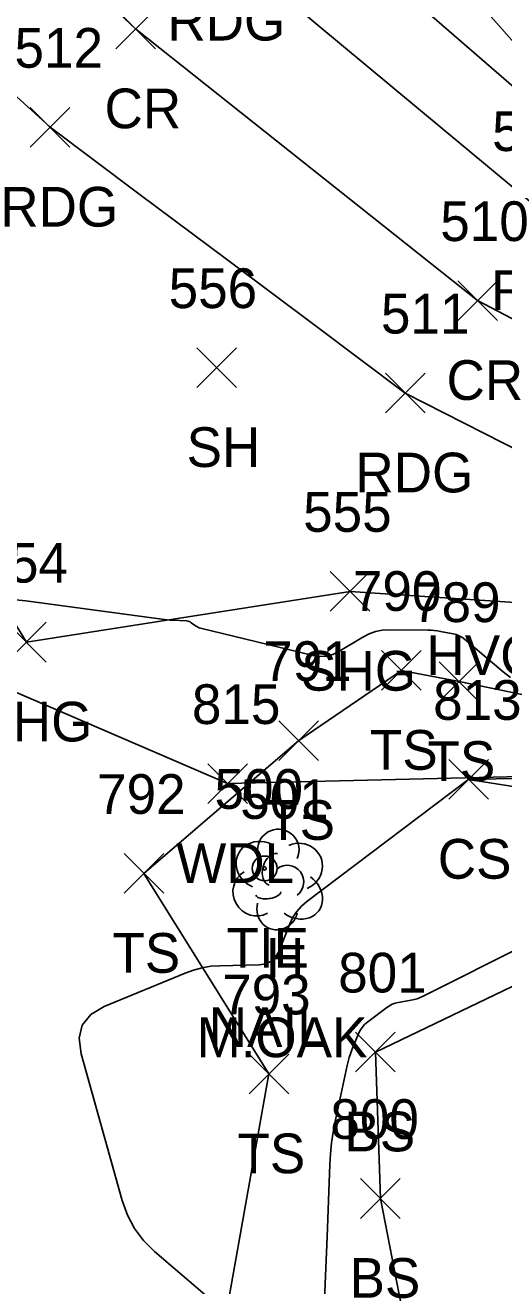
# Model space of a CAD drawing. Extents: x 1592612 to 1596497, y 111838 to 113741.
# Drawn here: x 1592810.3 to 1592834.4, y 113419.9 to 113483.4 of the extents above; entities that cross this region are included whole.
import ezdxf

# ---------------------------------------------------------------- set-up
doc = ezdxf.new("R2010")
doc.units = 0
for name, color, linetype in [('C_A', 7, 'Continuous'), ('C_C', 7, 'Continuous'), ('C_I', 7, 'Continuous'), ('CBP', 7, 'Continuous'), ('L_A', 7, 'Continuous'), ('L_C', 7, 'Continuous'), ('L_I', 7, 'Continuous'), ('L_TIC', 7, 'Continuous'), ('LAWA', 7, 'Continuous'), ('LELB', 7, 'Continuous'), ('LSOGCMI', 7, 'Continuous'), ('LTD', 7, 'Continuous'), ('P_A', 7, 'Continuous'), ('P_I', 7, 'Continuous'), ('P_TIC', 7, 'Continuous'), ('PEU', 7, 'Continuous'), ('PRC', 7, 'Continuous'), ('PSU', 7, 'Continuous'), ('RGR', 7, 'Continuous')]:
    doc.layers.add(name, color=color, linetype=linetype)

msp = doc.modelspace()

# ---------------------------------------------------------------- linework, layer by layer
at = {"layer": 'CBP'}
for radius in [0.625, 0.0833]:
    msp.add_circle((1592822.362, 113440.933), radius, dxfattribs=at)
at = {"layer": 'L_TIC'}
for points in [[(1592818.939, 113465.147), (1592820.939, 113467.147)], [(1592820.939, 113465.147), (1592818.939, 113467.147)], [(1592828.258, 113449.901), (1592830.258, 113451.901)], [(1592830.258, 113449.901), (1592828.258, 113451.901)], [(1592831.164, 113449.338), (1592833.164, 113451.338)], [(1592833.164, 113449.338), (1592831.164, 113451.338)], [(1592823.082, 113446.372), (1592825.082, 113448.372)], [(1592825.082, 113446.372), (1592823.082, 113448.372)], [(1592819.49, 113444.204), (1592821.49, 113446.204)], [(1592821.49, 113444.204), (1592819.49, 113446.204)], [(1592831.649, 113444.415), (1592833.649, 113446.415)], [(1592833.649, 113444.415), (1592831.649, 113446.415)], [(1592815.277, 113439.679), (1592817.277, 113441.679)], [(1592817.277, 113439.679), (1592815.277, 113441.679)], [(1592826.942, 113430.685), (1592828.942, 113432.685)], [(1592828.942, 113430.685), (1592826.942, 113432.685)], [(1592821.58, 113429.583), (1592823.58, 113431.583)], [(1592823.58, 113429.583), (1592821.58, 113431.583)], [(1592827.202, 113423.312), (1592829.202, 113425.312)], [(1592829.202, 113423.312), (1592827.202, 113425.312)]]:
    msp.add_lwpolyline(points, dxfattribs=at)
at = {"layer": 'LAWA'}
for points in [[(1592820.49, 113445.204), (1592799.578, 113454.201), (1592791.672, 113482.437), (1592778.021, 113504.51), (1592763.403, 113519.793), (1592739.369, 113545.558), (1592709.175, 113565.248), (1592691.74, 113580.372), (1592683.654, 113590.995), (1592666.454, 113606.066), (1592652.114, 113621.499)], [(1592855.743, 113446.044), (1592820.49, 113445.204)]]:
    msp.add_lwpolyline(points, dxfattribs=at)
at = {"layer": 'LELB'}
for points in [[(1592847.913, 113452.033), (1592842.334, 113448.243), (1592832.164, 113450.338), (1592829.258, 113450.901), (1592824.082, 113447.372), (1592816.277, 113440.679), (1592822.58, 113430.583), (1592819.462, 113413.131), (1592816.667, 113392.753), (1592812.967, 113379.234)], [(1592838.171, 113444.533), (1592832.649, 113445.415)], [(1592823.87, 113376.529), (1592829.701, 113394.688), (1592831.503, 113407.397), (1592828.202, 113424.312), (1592827.942, 113431.685), (1592842.578, 113438.689), (1592847.993, 113441.095), (1592853.522, 113431.624), (1592860.515, 113433.053)]]:
    msp.add_lwpolyline(points, dxfattribs=at)
at = {"layer": 'LSOGCMI'}
for points in [[(1592809.628, 113454.48), (1592810.315, 113454.414), (1592817.176, 113453.476), (1592817.314, 113453.459), (1592817.451, 113453.445), (1592817.589, 113453.434), (1592817.728, 113453.426), (1592818.423, 113453.394), (1592818.489, 113453.386), (1592818.551, 113453.369), (1592818.61, 113453.343), (1592818.665, 113453.307), (1592818.881, 113453.146), (1592818.936, 113453.109), (1592818.994, 113453.077), (1592819.055, 113453.052), (1592819.119, 113453.033), (1592824.807, 113451.652), (1592825.146, 113451.601), (1592825.476, 113451.618), (1592825.795, 113451.701), (1592826.103, 113451.85), (1592827.318, 113452.582), (1592827.628, 113452.742), (1592827.95, 113452.856), (1592828.286, 113452.923), (1592828.634, 113452.944), (1592830.587, 113452.933), (1592830.749, 113452.929), (1592830.91, 113452.917), (1592831.07, 113452.897), (1592831.229, 113452.871), (1592831.865, 113452.749), (1592832.02, 113452.709), (1592832.165, 113452.65), (1592832.302, 113452.574), (1592832.43, 113452.478), (1592834.381, 113450.825), (1592834.76, 113450.539)], [(1592819.598, 113419.261), (1592816.813, 113421.647), (1592816.259, 113422.194), (1592815.802, 113422.803), (1592815.442, 113423.475), (1592815.18, 113424.208), (1592813.118, 113431.594), (1592813.011, 113432.383), (1592813.169, 113433.043), (1592813.592, 113433.575), (1592814.278, 113433.978), (1592818.353, 113435.665), (1592818.776, 113435.818), (1592819.208, 113435.931), (1592819.649, 113436.003), (1592820.098, 113436.035), (1592822.084, 113436.085), (1592822.422, 113436.136), (1592822.702, 113436.269), (1592822.925, 113436.486), (1592823.09, 113436.785), (1592823.634, 113438.149), (1592823.79, 113438.475), (1592823.984, 113438.771), (1592824.218, 113439.037), (1592824.492, 113439.273), (1592832.582, 113445.378), (1592832.597, 113445.39), (1592832.632, 113445.418), (1592832.636, 113445.42), (1592832.642, 113445.425), (1592832.644, 113445.425), (1592832.65, 113445.424), (1592836.766, 113445.482)], [(1592825.372, 113419.23), (1592825.415, 113420.018), (1592825.453, 113420.806), (1592825.488, 113421.595), (1592825.518, 113422.383), (1592825.649, 113426.019), (1592825.68, 113426.566), (1592825.736, 113427.11), (1592825.815, 113427.652), (1592825.919, 113428.19), (1592826.523, 113431.005), (1592826.571, 113431.207), (1592826.627, 113431.406), (1592826.691, 113431.603), (1592826.764, 113431.797), (1592827.072, 113432.568), (1592827.16, 113432.752), (1592827.27, 113432.919), (1592827.402, 113433.069), (1592827.557, 113433.203), (1592828.518, 113433.928), (1592828.652, 113434.018), (1592828.793, 113434.09), (1592828.943, 113434.144), (1592829.1, 113434.181), (1592829.742, 113434.294), (1592829.901, 113434.327), (1592830.056, 113434.372), (1592830.208, 113434.429), (1592830.355, 113434.496), (1592840.833, 113439.755)]]:
    msp.add_lwpolyline(points, dxfattribs=at)
at = {"layer": 'LTD'}
msp.add_line((1592823.004, 113440.427), (1592823.004, 113440.427), dxfattribs=at)
msp.add_line((1592823.004, 113440.427), (1592823.004, 113440.427), dxfattribs=at)
msp.add_arc((1592823.051, 113441.861), 1.047, 335.52715, 180.95627, dxfattribs=at)
for centre, major_axis, ratio, start_param, end_param in [((1592822.212, 113441.094), (1.21, -0.512), 0.895232, 1.570796, 4.712389), ((1592824.046, 113441.011), (-1.141, -0.483), 0.949671, 1.570796, 4.712389), ((1592822.796, 113440.885), (-0.208, -0.792), 0.645439, 3.141593, 6.283185), ((1592823.504, 113440.261), (-0.5, 0.667), 0.989748, 3.141593, 6.283185), ((1592821.921, 113439.719), (0.584, -1.042), 0.959034, 3.141593, 6.283185), ((1592824.004, 113439.594), (-1.09, 0.792), 0.841452, 1.570796, 4.712389), ((1592822.546, 113439.677), (-0.625, -0.083), 0.423636, 0, 3.141593), ((1592823.004, 113438.927), (0.265, 1.061), 0.942809, 1.570796, 4.712389)]:
    msp.add_ellipse(centre, major_axis=major_axis, ratio=ratio, start_param=start_param, end_param=end_param, dxfattribs=at)
at = {"layer": 'P_TIC'}
for points in [[(1592814.857, 113482.202), (1592816.857, 113484.202)], [(1592816.857, 113482.202), (1592814.857, 113484.202)], [(1592810.546, 113477.25), (1592812.546, 113479.25)], [(1592812.546, 113477.25), (1592810.546, 113479.25)], [(1592832.097, 113468.523), (1592834.097, 113470.523)], [(1592834.097, 113468.523), (1592832.097, 113470.523)], [(1592828.452, 113463.867), (1592830.452, 113465.867)], [(1592830.452, 113463.867), (1592828.452, 113465.867)], [(1592825.665, 113453.883), (1592827.665, 113455.883)], [(1592827.665, 113453.883), (1592825.665, 113455.883)], [(1592809.348, 113451.325), (1592811.348, 113453.325)], [(1592811.348, 113451.325), (1592809.348, 113453.325)]]:
    msp.add_lwpolyline(points, dxfattribs=at)
at = {"layer": 'PEU'}
for points in [[(1592852.273, 113463.849), (1592836.279, 113474.056), (1592819.972, 113487.621), (1592800.662, 113505.499), (1592780.779, 113527.086), (1592759.62, 113549.571), (1592738.37, 113572.943), (1592716.192, 113596.277), (1592693.964, 113619.189), (1592672.676, 113639.672)], [(1592849.263, 113454.813), (1592844.314, 113457.324), (1592839.36, 113459.838), (1592834.406, 113462.353), (1592829.452, 113464.867), (1592824.976, 113468.213), (1592820.499, 113471.559), (1592816.022, 113474.905), (1592811.546, 113478.25), (1592806.466, 113482.857), (1592801.387, 113487.463), (1592796.307, 113492.07), (1592791.228, 113496.676), (1592786.246, 113502.157), (1592781.265, 113507.638), (1592776.283, 113513.119), (1592771.302, 113518.6), (1592765.981, 113524.318), (1592760.66, 113530.036), (1592755.339, 113535.754), (1592750.018, 113541.472), (1592744.662, 113547.12), (1592739.305, 113552.768)]]:
    msp.add_lwpolyline(points, dxfattribs=at)
at = {"layer": 'PRC'}
msp.add_lwpolyline([(1592851.008, 113460.149), (1592833.097, 113469.523), (1592815.857, 113483.202), (1592796.573, 113501.275), (1592777.295, 113523.934), (1592756.259, 113546.33), (1592734.615, 113569.346), (1592712.839, 113593.061), (1592690.495, 113615.302), (1592669.477, 113636.459)], dxfattribs=at)
at = {"layer": 'PSU'}
for points in [[(1592736.914, 113550.763), (1592742.37, 113545.281), (1592747.826, 113539.8), (1592753.219, 113534.098), (1592758.612, 113528.396), (1592764.004, 113522.694), (1592769.397, 113516.992), (1592775.088, 113510.156), (1592780.779, 113503.319), (1592784.293, 113498.187), (1592787.807, 113493.055), (1592790.997, 113487.112), (1592794.187, 113481.168), (1592797.377, 113475.225), (1592800.567, 113469.281), (1592805.227, 113460.599), (1592810.348, 113452.325), (1592818.506, 113453.604), (1592826.665, 113454.883), (1592832.198, 113454.513), (1592837.731, 113454.142), (1592843.264, 113453.772), (1592848.786, 113453.402)], [(1592770.049, 113548.457), (1592775.263, 113542.835), (1592780.478, 113537.214), (1592785.693, 113531.593), (1592790.602, 113526.158), (1592795.512, 113520.723), (1592800.422, 113515.288), (1592805.331, 113509.853), (1592809.758, 113505.035), (1592814.184, 113500.218), (1592818.611, 113495.4), (1592823.037, 113490.583), (1592826.914, 113487.218), (1592830.791, 113483.853), (1592834.668, 113480.488), (1592838.545, 113477.123), (1592845.634, 113471.053), (1592852.707, 113464.996)]]:
    msp.add_lwpolyline(points, dxfattribs=at)
at = {"layer": 'RGR'}
msp.add_lwpolyline([(1592817.747, 113502.377), (1592829.033, 113489.186), (1592839.839, 113476.992), (1592847.811, 113468.949), (1592852.564, 113465.029)], dxfattribs=at)
msp.add_lwpolyline([(1592817.747, 113502.377), (1592829.033, 113489.186), (1592839.839, 113476.992), (1592847.811, 113468.949), (1592852.564, 113465.029)], dxfattribs=at)

# ---------------------------------------------------------------- texts
at = {"layer": 'C_A'}
for s, p in [('HVCTRL', (1592830.519, 113450.667)), ('TIE', (1592820.44, 113435.933))]:
    msp.add_text(s, height=2, dxfattribs=at).set_placement(p)
at = {"layer": 'C_C'}
msp.add_text('NAIL', height=2, dxfattribs=at).set_placement((1592819.543, 113431.933))
at = {"layer": 'C_I'}
msp.add_text('500', height=2, dxfattribs=at).set_placement((1592819.834, 113443.933))
at = {"layer": 'L_A'}
for s, p in [('SH', (1592818.427, 113461.147)), ('TS', (1592827.668, 113445.901)), ('TS', (1592830.573, 113445.338)), ('TS', (1592822.491, 113442.372)), ('CS', (1592831.09, 113440.415)), ('WDL', (1592817.907, 113440.204)), ('TS', (1592814.686, 113435.679)), ('H', (1592822.437, 113435.427)), ('BS', (1592826.383, 113426.685)), ('TS', (1592820.99, 113425.583)), ('BS', (1592826.643, 113419.312))]:
    msp.add_text(s, height=2, dxfattribs=at).set_placement(p)
at = {"layer": 'L_C'}
msp.add_text('M.OAK', height=2, dxfattribs=at).set_placement((1592818.925, 113431.427))
at = {"layer": 'L_I'}
for s, p in [('556', (1592817.522, 113469.147)), ('790', (1592826.81, 113453.901)), ('789', (1592829.794, 113453.338)), ('791', (1592822.286, 113450.372)), ('815', (1592818.695, 113448.204)), ('813', (1592830.854, 113448.415)), ('792', (1592813.914, 113443.679)), ('501', (1592821.13, 113443.427)), ('801', (1592826.068, 113434.685)), ('793', (1592820.218, 113433.583)), ('800', (1592825.674, 113427.312))]:
    msp.add_text(s, height=2, dxfattribs=at).set_placement(p)
at = {"layer": 'P_A'}
for s, p in [('RDG', (1592817.46, 113482.621)), ('CR', (1592814.29, 113478.202)), ('RDG', (1592809.034, 113473.25)), ('RDG', (1592833.767, 113469.056)), ('CR', (1592831.531, 113464.523)), ('RDG', (1592826.94, 113459.867)), ('SHG', (1592824.2, 113449.883)), ('SHG', (1592807.883, 113447.325))]:
    msp.add_text(s, height=2, dxfattribs=at).set_placement(p)
at = {"layer": 'P_I'}
for s, p in [('512', (1592809.751, 113481.25)), ('509', (1592833.83, 113477.056)), ('510', (1592831.216, 113472.523)), ('511', (1592828.224, 113467.867)), ('555', (1592824.303, 113457.883)), ('554', (1592807.986, 113455.325))]:
    msp.add_text(s, height=2, dxfattribs=at).set_placement(p)

doc.saveas('drawing.dxf')
